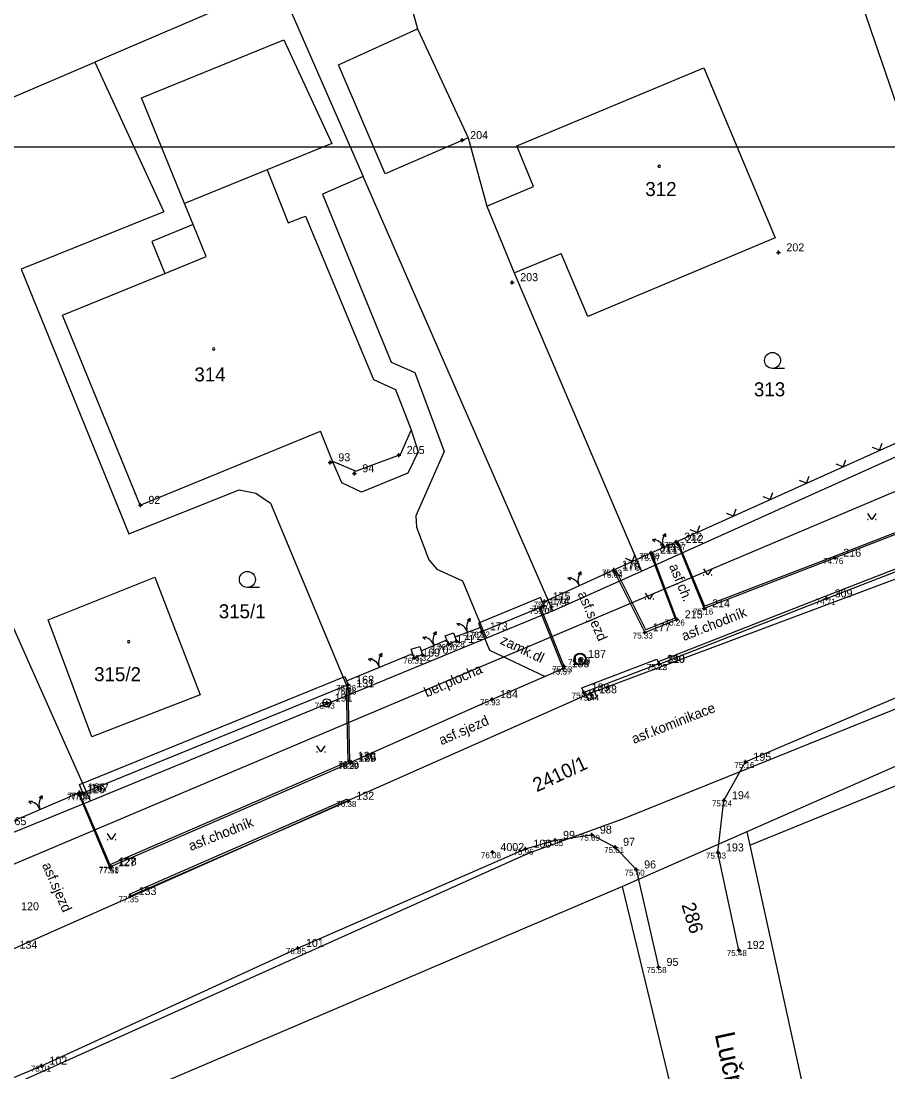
# Model space of a CAD drawing. Extents: x -454285 to -453563, y -1108687 to -1108249.
# Drawn here: x -454018.7 to -453975.4, y -1108516.1 to -1108463.6 of the extents above; entities that cross this region are included whole.
import ezdxf

# ---------------------------------------------------------------- set-up
doc = ezdxf.new("R2010")
doc.units = 0
for name, color, linetype in [('1', 7, 'Continuous'), ('14', 7, 'Continuous'), ('15', 7, 'Continuous'), ('16', 7, 'Continuous'), ('2', 7, 'Continuous'), ('23', 7, 'Continuous'), ('25', 7, 'Continuous'), ('38', 7, 'Continuous'), ('BODY_T1_2018', 7, 'Continuous'), ('CISLA_T1_2018', 7, 'Continuous'), ('obrubník', 7, 'Continuous'), ('okraj asf.komunikace', 7, 'Continuous'), ('oplocení', 7, 'Continuous'), ('palisada', 7, 'Continuous'), ('rozhraní', 7, 'Continuous'), ('rámy', 7, 'Continuous'), ('sloup', 7, 'Continuous'), ('T', 7, 'Continuous'), ('uliční vpusť', 7, 'Continuous'), ('VYSKY_T1_2018', 7, 'Continuous'), ('zeleň', 7, 'Continuous'), ('šachtice', 7, 'Continuous')]:
    doc.layers.add(name, color=color, linetype=linetype)

# ---------------------------------------------------------------- blocks, each defined once
blk = doc.blocks.new('Z402')
for start, end in [(0, 180), (180, 0)]:
    blk.add_arc((0, 0), 0.15, start, end)
blk = doc.blocks.new('Z3040')
blk.add_line((1.5, 0), (0, 0))
blk.add_circle((0, 1), 1)
blk = doc.blocks.new('BRANKA')
for p, q in [((-0.351, 0.589), (-0.179, 0.552)), ((-0.351, 0.589), (-0.284, 0.449)), ((0.361, 0.583), (0.188, 0.549)), ((0.361, 0.583), (0.291, 0.445))]:
    blk.add_line(p, q)
for centre, start, end in [((-0.618, 0.03), 357.1751, 64.4688), ((0.619, 0.02), 114.5895, 181.8832)]:
    blk.add_arc(centre, 0.619, start, end)
blk = doc.blocks.new('EL.SLOUP')
blk.add_line((0.4, 0), (-0.4, 0))
blk.add_line((0.4, 0), (-0.4, 0))
blk.add_lwpolyline([(0.4, 0), (-0.4, 0)])
blk.add_lwpolyline([(0.4, 0), (-0.4, 0)])
blk.add_circle((0, 0), 0.4)
blk.add_circle((0, 0), 0.4)
for start, end in [(270, 0), (270, 0), (180, 270), (180, 270)]:
    blk.add_arc((0, 0), 0.4, start, end)
blk = doc.blocks.new('šachtice_kruh_velká')
for radius in [0.5, 0.495, 0.495, 0.455, 0.455, 0.45]:
    blk.add_circle((0, 0), radius)
blk = doc.blocks.new('vpusť')
for p, q in [((0.25, 0.25), (-0.25, 0.25)), ((-0.25, 0.25), (-0.25, -0.25)), ((-0.25, 0), (0.25, 0)), ((0.25, -0.25), (0.25, 0.25)), ((-0.25, -0.25), (0.25, -0.25))]:
    blk.add_line(p, q)
blk = doc.blocks.new('PARK')
for p, q in [((0, 0), (-1, 1.5)), ((1, 1.5), (0, 0))]:
    blk.add_line(p, q)
for centre, start, end in [((-1, 0), 0, 180), ((1, 0), 0, 180), ((1, 0), 180, 0), ((-1, 0), 180, 0)]:
    blk.add_arc(centre, 0.05, start, end)
blk = doc.blocks.new('PLOT05')
for q in [(-0.265, 0.265), (0.265, 0.265)]:
    blk.add_line((0, 0), q)
blk = doc.blocks.new('POINT_DISPLAY')
for p, q in [((-0.1, 0), (0.1, 0)), ((0, -0.1), (0, 0.1))]:
    blk.add_line(p, q)
blk.add_circle((0, 0), 0.05)
blk = doc.blocks.new('t1_2018')
at = {"layer": 'BODY_T1_2018'}
for p in [(-453996.63, -1108469.52), (-453980.83, -1108475.13), (-453994.13, -1108476.62), (-453999.8, -1108485.26), (-454003.22, -1108485.62), (-454002.02, -1108486.17), (-454012.71, -1108487.75), (-453985.94, -1108489.59), (-453985.86, -1108489.7), (-453987.18, -1108490.14), (-453987.14, -1108490.24), (-453977.99, -1108490.39), (-453989.05, -1108490.98), (-453989.02, -1108491.08), (-453992.51, -1108492.57), (-453978.42, -1108492.42), (-453992.7, -1108492.89), (-453992.55, -1108492.78), (-453984.54, -1108492.92), (-453985.91, -1108493.47), (-453995.65, -1108494.07), (-453987.51, -1108494.12), (-453997.32, -1108494.7), (-453996.91, -1108494.55), (-453998.61, -1108495.24), (-453999.03, -1108495.38), (-453990.74, -1108495.45), (-453986.81, -1108495.69), (-453986.79, -1108495.7), (-453991.57, -1108495.92), (-453991.53, -1108495.81), (-454002.33, -1108496.74), (-454002.32, -1108496.92), (-453990.56, -1108497.12), (-453990.19, -1108497.22), (-454003.4, -1108497.63), (-453995.14, -1108497.46), (-454002.25, -1108500.54), (-454002.23, -1108500.64), (-454002.21, -1108500.62), (-453982.48, -1108500.59), (-454015.78, -1108502.21), (-454015.75, -1108502.12), (-454015.59, -1108502.14), (-454002.32, -1108502.54), (-453983.55, -1108502.51), (-453991.99, -1108504.49), (-453990.15, -1108504.23), (-453995.12, -1108505.1), (-453993.47, -1108504.93), (-453988.99, -1108504.84), (-453983.85, -1108505.12), (-454014.24, -1108505.86), (-454014.19, -1108505.82), (-453987.94, -1108505.97), (-454013.2, -1108507.3), (-454004.84, -1108509.89), (-453982.81, -1108509.99), (-453986.82, -1108510.84), (-454017.66, -1108515.77)]:
    blk.add_blockref('POINT_DISPLAY', p, dxfattribs=at)
at = {"layer": 'CISLA_T1_2018'}
for s, p in [('204', (-453996.23, -1108469.46)), ('202', (-453980.43, -1108475.07)), ('203', (-453993.73, -1108476.56)), ('93', (-454002.82, -1108485.56)), ('205', (-453999.4, -1108485.2)), ('94', (-454001.62, -1108486.11)), ('92', (-454012.31, -1108487.69)), ('312', (-453985.54, -1108489.53)), ('212', (-453985.46, -1108489.64)), ('311', (-453986.78, -1108490.08)), ('211', (-453986.74, -1108490.18)), ('216', (-453977.59, -1108490.33)), ('176', (-453988.65, -1108490.92)), ('178', (-453988.62, -1108491.02)), ('309', (-453978.02, -1108492.36)), ('179', (-453992.3, -1108492.83)), ('174', (-453992.15, -1108492.72)), ('175', (-453992.11, -1108492.51)), ('214', (-453984.14, -1108492.86)), ('215', (-453985.51, -1108493.41)), ('172', (-453996.51, -1108494.49)), ('173', (-453995.25, -1108494.01)), ('177', (-453987.11, -1108494.06)), ('171', (-453996.92, -1108494.64)), ('169', (-453998.63, -1108495.32)), ('170', (-453998.21, -1108495.18)), ('187', (-453990.34, -1108495.39)), ('183', (-453991.17, -1108495.86)), ('180', (-453991.13, -1108495.75)), ('310', (-453986.39, -1108495.64)), ('190', (-453986.41, -1108495.63)), ('168', (-454001.93, -1108496.68)), ('131', (-454001.92, -1108496.86)), ('189', (-453990.16, -1108497.06)), ('191', (-454003, -1108497.57)), ('184', (-453994.74, -1108497.4)), ('188', (-453989.79, -1108497.16)), ('130', (-454001.85, -1108500.48)), ('129', (-454001.83, -1108500.58)), ('185', (-454001.81, -1108500.56)), ('195', (-453982.08, -1108500.53)), ('126', (-454015.38, -1108502.15)), ('166', (-454015.35, -1108502.06)), ('167', (-454015.19, -1108502.08)), ('132', (-454001.92, -1108502.48)), ('194', (-453983.15, -1108502.45)), ('165', (-454019.3, -1108503.75)), ('99', (-453991.59, -1108504.43)), ('98', (-453989.75, -1108504.17)), ('100', (-453993.07, -1108504.87)), ('97', (-453988.59, -1108504.78)), ('4002', (-453994.72, -1108505.04)), ('193', (-453983.45, -1108505.06)), ('127', (-454013.84, -1108505.8)), ('128', (-454013.79, -1108505.76)), ('96', (-453987.54, -1108505.91)), ('133', (-454012.8, -1108507.24)), ('120', (-454018.67, -1108508)), ('134', (-454018.75, -1108509.92)), ('101', (-454004.44, -1108509.83)), ('192', (-453982.41, -1108509.93)), ('95', (-453986.42, -1108510.78)), ('102', (-454017.26, -1108515.71))]:
    blk.add_text(s, height=0.4, dxfattribs=at).set_placement(p)
at = {"layer": 'VYSKY_T1_2018'}
for s, p in [('75.37', (-453986.54, -1108489.89)), ('75.37', (-453986.46, -1108490)), ('75.38', (-453987.78, -1108490.44)), ('75.37', (-453987.74, -1108490.54)), ('74.76', (-453978.59, -1108490.69)), ('75.63', (-453989.65, -1108491.28)), ('75.64', (-453989.62, -1108491.38)), ('74.71', (-453978.97, -1108492.72)), ('75.70', (-453993.275, -1108493.19)), ('75.74', (-453993.15, -1108493.08)), ('75.71', (-453993.06, -1108492.87)), ('75.16', (-453985.09, -1108493.22)), ('75.26', (-453986.51, -1108493.77)), ('76.22', (-453996.25, -1108494.37)), ('76.28', (-453997.51, -1108494.85)), ('75.33', (-453988.11, -1108494.42)), ('76.30', (-453997.895, -1108495)), ('76.31', (-453999.58, -1108495.68)), ('76.32', (-453999.21, -1108495.54)), ('75.53', (-453991.34, -1108495.75)), ('75.57', (-453992.17, -1108496.22)), ('75.53', (-453992.13, -1108496.11)), ('75.22', (-453987.41, -1108495.99)), ('75.23', (-453987.39, -1108496)), ('76.36', (-454002.93, -1108497.04)), ('76.36', (-454002.92, -1108497.22)), ('75.45', (-453991.16, -1108497.42)), ('75.44', (-453990.79, -1108497.52)), ('76.43', (-454004, -1108497.93)), ('75.93', (-453995.74, -1108497.76)), ('76.29', (-454002.83, -1108500.94)), ('76.30', (-454002.825, -1108500.84)), ('76.30', (-454002.785, -1108500.92)), ('75.16', (-453983.03, -1108500.89)), ('77.78', (-454016.38, -1108502.51)), ('77.78', (-454016.35, -1108502.42)), ('77.73', (-454016.19, -1108502.44)), ('75.24', (-453984.15, -1108502.81)), ('76.38', (-454002.92, -1108502.84)), ('75.85', (-453992.59, -1108504.79)), ('75.69', (-453990.75, -1108504.53)), ('76.08', (-453995.695, -1108505.4)), ('75.96', (-453994.07, -1108505.23)), ('75.61', (-453989.54, -1108505.14)), ('75.43', (-453984.45, -1108505.42)), ('77.48', (-454014.79, -1108506.12)), ('77.51', (-454014.79, -1108506.16)), ('75.60', (-453988.515, -1108506.27)), ('77.35', (-454013.8, -1108507.6)), ('76.85', (-454005.44, -1108510.19)), ('75.48', (-453983.41, -1108510.29)), ('75.58', (-453987.42, -1108511.14)), ('78.01', (-454018.185, -1108516.07))]:
    blk.add_text(s, height=0.3, dxfattribs=at).set_placement(p)

msp = doc.modelspace()

# ---------------------------------------------------------------- linework, layer by layer
at = {"layer": '1'}
for p, q in [((-453969.717, -1108482.961), (-453980.277, -1108452.101)), ((-454000.077, -1108459.531), (-453998.857, -1108463.941)), ((-454005.797, -1108461.671), (-454014.987, -1108465.611)), ((-454005.797, -1108461.671), (-454001.587, -1108471.321)), ((-453998.857, -1108463.941), (-453996.327, -1108469.401)), ((-454028.997, -1108471.611), (-454014.987, -1108465.611)), ((-454014.987, -1108465.611), (-454011.547, -1108473.091)), ((-453993.907, -1108469.801), (-453984.557, -1108465.891)), ((-453984.557, -1108465.891), (-453980.997, -1108474.401)), ((-453996.327, -1108469.401), (-453995.407, -1108472.811)), ((-453993.067, -1108471.831), (-453993.907, -1108469.801)), ((-453992.107, -1108493.041), (-454001.587, -1108471.321)), ((-454015.197, -1108502.531), (-454028.997, -1108471.611)), ((-453995.407, -1108472.811), (-453993.067, -1108471.831)), ((-454011.547, -1108473.091), (-454018.667, -1108475.961)), ((-453980.997, -1108474.401), (-453990.357, -1108478.321)), ((-453994.027, -1108476.151), (-453991.677, -1108475.171)), ((-453990.357, -1108478.321), (-453991.677, -1108475.171)), ((-454018.667, -1108475.961), (-454013.287, -1108489.181)), ((-453994.027, -1108476.151), (-453987.677, -1108491.051)), ((-453987.677, -1108491.051), (-453969.717, -1108482.961)), ((-453969.347, -1108484.681), (-454124.757, -1108550.421)), ((-454013.287, -1108489.181), (-454007.767, -1108486.991)), ((-454007.767, -1108486.991), (-454006.947, -1108487.161)), ((-454006.947, -1108487.161), (-454006.207, -1108487.661)), ((-454006.207, -1108487.661), (-454002.227, -1108497.201)), ((-454017.317, -1108493.481), (-454011.997, -1108491.351)), ((-454011.997, -1108491.351), (-454009.727, -1108497.241)), ((-453992.107, -1108493.041), (-453987.677, -1108491.051)), ((-453992.107, -1108493.041), (-453995.417, -1108494.401)), ((-454015.137, -1108499.331), (-454017.317, -1108493.481)), ((-453995.417, -1108494.401), (-454002.047, -1108497.131)), ((-454015.197, -1108502.531), (-454002.227, -1108497.201)), ((-454009.727, -1108497.241), (-454015.137, -1108499.331)), ((-454002.227, -1108497.201), (-454002.047, -1108497.131)), ((-453968.587, -1108497.991), (-453982.407, -1108504.081)), ((-454038.597, -1108512.101), (-454015.197, -1108502.531)), ((-453982.407, -1108504.081), (-453988.627, -1108506.811)), ((-453982.407, -1108504.081), (-453982.257, -1108504.751)), ((-453982.257, -1108504.751), (-453979.297, -1108518.271)), ((-453988.627, -1108506.811), (-454099.187, -1108553.971)), ((-453979.987, -1108542.331), (-453988.627, -1108506.811))]:
    msp.add_line(p, q, dxfattribs=at)
at = {"layer": '2'}
for p, q in [((-454002.807, -1108465.741), (-453998.857, -1108463.941)), ((-454012.657, -1108467.401), (-454005.537, -1108464.501)), ((-454005.537, -1108464.501), (-454003.147, -1108469.681)), ((-454000.477, -1108471.201), (-454002.807, -1108465.741)), ((-454010.507, -1108472.671), (-454012.657, -1108467.401)), ((-453996.327, -1108469.401), (-454000.477, -1108471.201)), ((-454003.147, -1108469.681), (-454005.727, -1108470.731)), ((-454005.727, -1108470.731), (-454006.377, -1108471.001)), ((-454006.377, -1108471.001), (-454010.507, -1108472.671)), ((-454006.377, -1108471.001), (-454005.327, -1108473.651)), ((-454001.587, -1108471.321), (-454003.617, -1108472.211)), ((-454003.617, -1108472.211), (-454000.177, -1108480.611)), ((-454010.077, -1108473.731), (-454010.507, -1108472.671)), ((-453995.407, -1108472.811), (-453994.027, -1108476.151)), ((-454005.327, -1108473.651), (-454004.637, -1108473.381)), ((-454004.637, -1108473.381), (-454004.467, -1108473.311)), ((-454004.467, -1108473.311), (-454001.057, -1108481.481)), ((-454010.077, -1108473.731), (-454012.137, -1108474.571)), ((-454009.427, -1108475.331), (-454010.077, -1108473.731)), ((-454012.137, -1108474.571), (-454011.487, -1108476.171)), ((-454011.487, -1108476.171), (-454009.427, -1108475.331)), ((-454016.597, -1108478.251), (-454011.487, -1108476.171)), ((-454012.727, -1108487.751), (-454016.597, -1108478.251)), ((-454000.177, -1108480.611), (-453998.997, -1108481.131)), ((-454001.057, -1108481.481), (-453999.967, -1108481.981)), ((-453998.997, -1108481.131), (-453997.537, -1108485.071)), ((-453999.967, -1108481.981), (-453999.177, -1108483.991)), ((-454012.727, -1108487.751), (-454003.717, -1108484.061)), ((-454003.107, -1108485.551), (-454003.717, -1108484.061)), ((-453999.177, -1108483.991), (-453999.737, -1108485.231)), ((-453999.177, -1108483.991), (-453998.837, -1108485.081)), ((-453998.837, -1108485.081), (-453999.347, -1108486.161)), ((-453997.537, -1108485.071), (-453998.947, -1108488.281)), ((-454002.637, -1108486.631), (-454003.107, -1108485.551)), ((-454003.107, -1108485.551), (-454001.927, -1108486.051)), ((-453999.737, -1108485.231), (-454001.927, -1108486.051)), ((-453999.347, -1108486.161), (-454001.667, -1108487.101)), ((-454001.667, -1108487.101), (-454002.637, -1108486.631)), ((-453990.237, -1108497.151), (-453963.087, -1108486.981)), ((-453998.947, -1108488.281), (-453998.917, -1108488.861)), ((-453998.917, -1108488.861), (-453998.297, -1108490.481)), ((-453998.297, -1108490.481), (-453997.897, -1108490.951)), ((-453997.897, -1108490.951), (-453996.607, -1108491.541)), ((-453996.607, -1108491.541), (-453995.597, -1108493.981)), ((-453962.267, -1108492.821), (-453988.537, -1108503.411)), ((-453995.597, -1108493.981), (-453995.417, -1108494.401)), ((-453982.257, -1108504.751), (-453960.007, -1108495.681)), ((-454063.887, -1108529.801), (-453990.237, -1108497.151)), ((-453988.537, -1108503.411), (-453993.337, -1108505.161)), ((-453993.337, -1108505.161), (-454060.357, -1108535.251))]:
    msp.add_line(p, q, dxfattribs=at)
at = {"layer": 'obrubník'}
for points in [[(-453967.158, -1108481.736), (-453966.21, -1108485.89), (-453972.37, -1108488.21), (-453977.99, -1108490.39), (-453984.54, -1108492.92), (-453984.577, -1108492.827), (-453978.026, -1108490.297), (-453972.406, -1108488.117), (-453966.327, -1108485.827), (-453967.254, -1108481.766)], [(-453985.865, -1108489.556), (-453984.53, -1108492.808), (-453984.577, -1108492.827), (-453985.911, -1108489.577)], [(-453987.178, -1108490.139), (-453985.947, -1108493.377), (-453985.994, -1108493.395), (-453987.224, -1108490.16)], [(-453989.066, -1108490.987), (-453987.51, -1108494.12), (-453985.91, -1108493.47), (-453985.947, -1108493.377), (-453987.462, -1108493.992), (-453988.975, -1108490.946)], [(-454002.27, -1108500.548), (-454014.23, -1108505.728), (-454014.19, -1108505.82), (-454002.23, -1108500.64)], [(-454015.762, -1108502.125), (-454014.194, -1108505.841), (-454014.24, -1108505.86), (-454015.808, -1108502.145)], [(-454002.32, -1108502.54), (-454013.2, -1108507.3), (-454013.249, -1108507.19), (-454002.368, -1108502.43)]]:
    msp.add_lwpolyline(points, dxfattribs=at)
for points in [[(-453966.361, -1108487.687), (-453971.013, -1108489.408), (-453978.464, -1108492.308), (-453986.834, -1108495.588), (-453986.79, -1108495.7), (-453978.42, -1108492.42), (-453970.97, -1108489.52), (-453966.32, -1108487.8)], [(-453986.81, -1108495.69), (-453990.56, -1108497.12), (-453990.649, -1108496.886), (-453986.899, -1108495.456)], [(-454002.25, -1108500.54), (-454002.32, -1108496.92), (-454002.42, -1108496.922), (-454002.35, -1108500.542)]]:
    msp.add_lwpolyline(points, close=True, dxfattribs=at)
at = {"layer": 'okraj asf.komunikace'}
for points in [[(-453982.81, -1108509.99), (-453983.85, -1108505.12), (-453983.55, -1108502.51), (-453982.48, -1108500.59), (-453972.21, -1108496.2), (-453961.66, -1108492.56), (-453950.2, -1108489.09), (-453937.41, -1108485.39), (-453932.25, -1108484.37), (-453926.75, -1108483.25), (-453917, -1108481.33), (-453912.35, -1108480.49), (-453907.08, -1108479.77), (-453900.36, -1108478.91), (-453893.38, -1108478.37), (-453887.02, -1108478.23), (-453881.35, -1108478.03), (-453874.87, -1108478.15), (-453872.62, -1108479.21), (-453871.56, -1108480.92), (-453871.45, -1108482.5)], [(-454112.32, -1108555.84), (-454100.65, -1108550.87), (-454089.58, -1108546.38), (-454076.91, -1108541.3), (-454064.18, -1108535.73), (-454053.87, -1108531.55), (-454045.79, -1108528.05), (-454030.23, -1108521.06), (-454017.66, -1108515.77), (-454004.84, -1108509.89), (-453993.47, -1108504.93), (-453991.99, -1108504.49), (-453990.15, -1108504.23), (-453988.99, -1108504.84), (-453987.94, -1108505.97), (-453986.82, -1108510.84)]]:
    msp.add_lwpolyline(points, dxfattribs=at)
at = {"layer": 'oplocení'}
for p, q in [((-453996.987, -1108494.339), (-453995.736, -1108493.862)), ((-453998.681, -1108495.027), (-453997.397, -1108494.489)), ((-454002.415, -1108496.532), (-453999.101, -1108495.167))]:
    msp.add_line(p, q, dxfattribs=at)
for points in [[(-453992.51, -1108492.57), (-453989.05, -1108490.98), (-453987.18, -1108490.14), (-453985.94, -1108489.59), (-453970.3, -1108482.55)], [(-454125.24, -1108545.86), (-454124.84, -1108549.82), (-454113.81, -1108544.95), (-454112.8, -1108544.5), (-454100.47, -1108538.97), (-454097.57, -1108537.59), (-454092.06, -1108535.05), (-454080.32, -1108529.69), (-454079.35, -1108529.29), (-454075.63, -1108527.58), (-454069.87, -1108524.95), (-454066.24, -1108523.74), (-454058.33, -1108520.39), (-454057.22, -1108519.88), (-454050.24, -1108516.86), (-454045.48, -1108514.77), (-454020.87, -1108504.33), (-454019.7, -1108503.81), (-454015.75, -1108502.12)]]:
    msp.add_lwpolyline(points, dxfattribs=at)
for points in [[(-453992.723, -1108492.365), (-453995.823, -1108493.655), (-453995.65, -1108494.07), (-453992.55, -1108492.78)], [(-453996.91, -1108494.55), (-453997.32, -1108494.7), (-453997.475, -1108494.277), (-453997.065, -1108494.127)], [(-453998.61, -1108495.24), (-453999.03, -1108495.38), (-453999.172, -1108494.953), (-453998.752, -1108494.813)], [(-454015.76, -1108501.723), (-454002.5, -1108496.323), (-454002.33, -1108496.74), (-454015.59, -1108502.14)]]:
    msp.add_lwpolyline(points, close=True, dxfattribs=at)
at = {"layer": 'palisada'}
msp.add_lwpolyline([(-453992.809, -1108492.888), (-453991.623, -1108495.847), (-453991.53, -1108495.81), (-453992.716, -1108492.849)], close=True, dxfattribs=at)
at = {"layer": 'rozhraní'}
msp.add_line((-454002.27, -1108500.548), (-454002.23, -1108500.64), dxfattribs=at)
for points in [[(-453995.65, -1108494.07), (-453995.266, -1108494.993), (-453992.488, -1108496.316)], [(-453991.623, -1108495.847), (-453991.57, -1108495.92), (-453995.14, -1108497.46), (-454002.21, -1108500.62)]]:
    msp.add_lwpolyline(points, dxfattribs=at)
at = {"layer": 'rámy'}
msp.add_lwpolyline([(-454047.225, -1108469.854), (-453948.057, -1108469.854), (-453948.057, -1108529.906), (-454047.225, -1108529.906)], close=True, dxfattribs=at)

# ---------------------------------------------------------------- block references
msp.add_blockref('t1_2018', (0, 0))
at = {"layer": '23', "xscale": 0.4, "yscale": 0.4000000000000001}
for p in [(-453981.124, -1108480.923), (-454007.365, -1108491.869)]:
    msp.add_blockref('Z3040', p, dxfattribs=at)
at = {"layer": '25', "xscale": 0.4, "yscale": 0.4000000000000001}
for p in [(-453986.787, -1108470.821), (-454009.044, -1108479.949), (-454013.297, -1108494.571)]:
    msp.add_blockref('Z402', p, dxfattribs=at)
at = {"layer": 'oplocení'}
for name, p, rotation in [('PLOT05', (-453975.771, -1108485.013), 24.233838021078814), ('PLOT05', (-453977.595, -1108485.834), 24.233838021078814), ('PLOT05', (-453979.419, -1108486.655), 24.233838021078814), ('PLOT05', (-453981.243, -1108487.476), 24.233838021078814), ('PLOT05', (-453983.066, -1108488.296), 24.233838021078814), ('PLOT05', (-453984.89, -1108489.117), 24.233838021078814), ('BRANKA', (-453986.56, -1108489.865), 23.919602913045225), ('PLOT05', (-453988.115, -1108490.56), 24.18951415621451), ('BRANKA', (-453990.78, -1108491.775), 24.68055847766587), ('BRANKA', (-453996.362, -1108494.1), 20.850867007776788), ('BRANKA', (-453998.039, -1108494.758), 22.73055863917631), ('BRANKA', (-454000.758, -1108495.849), 22.38902981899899), ('BRANKA', (-454017.725, -1108502.965), 23.163568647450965)]:
    msp.add_blockref(name, p, dxfattribs=dict(at, rotation=rotation))
at = {"layer": 'sloup', "xscale": 0.5, "yscale": 0.5}
msp.add_blockref('EL.SLOUP', (-454003.4, -1108497.63), dxfattribs=at)
at = {"layer": 'uliční vpusť', "xscale": 0.9, "yscale": 0.8999999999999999, "rotation": 110.87351640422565}
msp.add_blockref('vpusť', (-453990.19, -1108497.22), dxfattribs=at)
at = {"layer": 'zeleň', "xscale": 0.2, "yscale": 0.20000000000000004}
for p in [(-453976.161, -1108488.473), (-453984.364, -1108491.238), (-453987.275, -1108492.445), (-454003.689, -1108500.09), (-454014.152, -1108504.468)]:
    msp.add_blockref('PARK', p, dxfattribs=at)
at = {"layer": 'šachtice', "xscale": 0.6, "yscale": 0.6}
msp.add_blockref('šachtice_kruh_velká', (-453990.74, -1108495.45), dxfattribs=at)

# ---------------------------------------------------------------- texts
at = {"layer": '14'}
for s, p in [('313', (-453982.053, -1108482.315)), ('315/1', (-454008.795, -1108493.408))]:
    msp.add_text(s, height=0.7, dxfattribs=at).set_placement(p)
msp.add_text('286', height=0.7, rotation=286.992, dxfattribs=at).set_placement((-453985.682, -1108507.73))
at = {"layer": '15'}
for s, p in [('312', (-453987.48, -1108472.305)), ('314', (-454010.013, -1108481.571)), ('315/2', (-454015.023, -1108496.551))]:
    msp.add_text(s, height=0.7, dxfattribs=at).set_placement(p)
at = {"layer": '16'}
msp.add_text('2410/1', height=0.7, rotation=25.1016, dxfattribs=at).set_placement((-453992.902, -1108502.107))
at = {"layer": '38'}
msp.add_text('Luční', height=1, rotation=282.186, dxfattribs=at).set_placement((-453984.017, -1108514.191))
at = {"layer": 'T'}
for s, rotation, p in [('asf.ch.', 292.3141, (-453986.302, -1108490.798)), ('asf.sjezd', 293.7821, (-453990.876, -1108492.183)), ('asf.chodník', 21.4825, (-453985.551, -1108494.546)), ('zamk.dl', 334.5337, (-453994.769, -1108494.665)), ('bet.plocha', 23.7821, (-453998.401, -1108497.368)), ('asf.kominikace', 21.4825, (-453988.048, -1108499.691)), ('asf.sjezd', 23.7821, (-453997.663, -1108499.758)), ('asf.chodník', 21.4825, (-454010.191, -1108505.041)), ('asf.sjezd', 293.782, (-454017.638, -1108505.735))]:
    msp.add_text(s, height=0.5, rotation=rotation, dxfattribs=at).set_placement(p)

doc.saveas('drawing.dxf')
